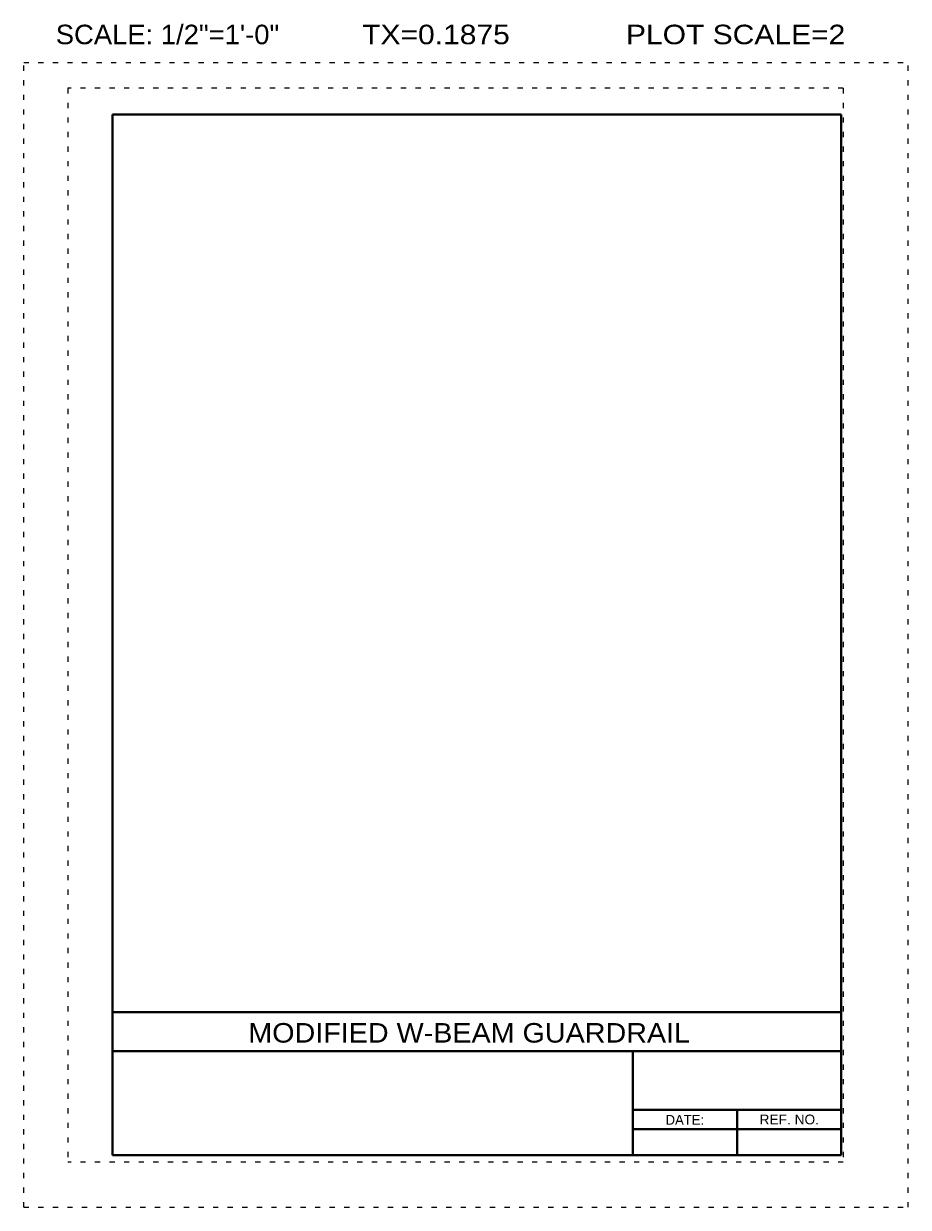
# Model space of a CAD drawing. Extents: x 1370 to 1387, y -905.5 to -882.8.
import ezdxf
from ezdxf.enums import TextEntityAlignment as Align

# ---------------------------------------------------------------- set-up
doc = ezdxf.new("R2010")
doc.units = 0
doc.header["$LTSCALE"] = 0.15
doc.linetypes.add('DOTTED', pattern=[1.5, 0.3, -1.2])
for name, color, linetype in [('57', 7, 'Continuous'), ('59', 7, 'Continuous'), ('9', 7, 'Continuous')]:
    doc.layers.add(name, color=color, linetype=linetype)
for name, color, linetype, lineweight in [('61', 7, 'DOTTED', 13), ('62', 7, 'DOTTED', 13), ('63', 7, 'Continuous', 40)]:
    doc.layers.add(name, color=color, linetype=linetype, lineweight=lineweight)

msp = doc.modelspace()

# ---------------------------------------------------------------- linework, layer by layer
at = {"layer": '61'}
for p, q in [((1385.75, -883.995), (1370.85, -883.995)), ((1370.85, -883.995), (1370.85, -904.63)), ((1385.75, -883.995), (1385.75, -904.63)), ((1385.75, -904.63), (1370.85, -904.63))]:
    msp.add_line(p, q, dxfattribs=at)
at = {"layer": '62'}
for p, q in [((1370, -905.5), (1370, -883.5)), ((1370, -883.5), (1387, -883.5)), ((1387, -905.5), (1387, -883.5)), ((1370, -905.5), (1387, -905.5))]:
    msp.add_line(p, q, dxfattribs=at)
at = {"layer": '63'}
for p, q in [((1371.7083, -884.5), (1371.7083, -904.5)), ((1371.7083, -884.5), (1385.7083, -884.5)), ((1385.7083, -884.5), (1385.7083, -904.5)), ((1371.7083, -901.75), (1385.7083, -901.75)), ((1371.7083, -902.5), (1385.7083, -902.5)), ((1381.7083, -904.5), (1381.7083, -902.5)), ((1381.7083, -903.625), (1385.7083, -903.625)), ((1383.7083, -904.5), (1383.7083, -903.625)), ((1381.7083, -904), (1385.7083, -904)), ((1371.7083, -904.5), (1385.7083, -904.5))]:
    msp.add_line(p, q, dxfattribs=at)

# ---------------------------------------------------------------- texts
at = {"layer": '57', "width": 1.1}
msp.add_text('MODIFIED W-BEAM GUARDRAIL', height=0.375, dxfattribs=at).set_placement((1374.3164, -902.3342))
at = {"layer": '59'}
msp.add_text('DATE:', height=0.1877, dxfattribs=at).set_placement((1382.7057, -903.9122), align=Align.CENTER)
at = {"layer": '59', "width": 1.05}
msp.add_text('REF. NO.', height=0.1877, dxfattribs=at).set_placement((1384.7121, -903.9055), align=Align.CENTER)
at = {"layer": '9'}
for s, width, p in [('SCALE: 1/2"=1\'-0"', 1.05, (1372.7637, -883.1488)), ('TX=0.1875', 1.15, (1377.9233, -883.1488)), ('PLOT SCALE=2', 1.15, (1383.6813, -883.1488))]:
    msp.add_text(s, height=0.375, dxfattribs=dict(at, width=width)).set_placement(p, align=Align.CENTER)

doc.saveas('drawing.dxf')
